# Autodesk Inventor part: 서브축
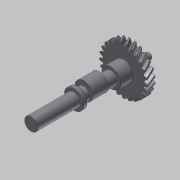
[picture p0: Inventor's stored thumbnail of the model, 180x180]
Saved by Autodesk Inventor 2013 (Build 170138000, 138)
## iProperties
Created: 2018-07
Part Number: 서브축
Material: 강철
Document SubType Name: Modeling
Designer: mduedu
Categories: <?xml version="1.0" encoding="UTF-16"?> <MemberInstance><Categories><FamilyTemplate><FamilyTemplateParameter ValueType="xs:double" Id="1" ObjectReferenceKey="da
Density: 7.85 g/cm^3
Mass: 513.764 g
Surface Area: 178.04 cm^2
Volume: 65.4477 cm^3
CustomPartVersion: 1
Author: mduedu
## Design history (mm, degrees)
sketch "Sketch1"
  geometry: C1 r 30.864 at (0, 0)
  constraints: 1 centre point
  dimensions: "d0" = 61.72879 diameter of C1 (= da_da)
extrude "Extrusion1" new body sketch "Sketch1" distance "d1" = 10 (= da_b); taper "d2" = 0 deg
workplane "Work Plane2"
sketch "Sketch2"
  geometry: C1 r 30.864 at (0, 0) reference; C2 r 29.013 at (0, 0)
  constraints: 1 centre point, 1 coincident
  dimensions: "d3" = 58.02632 diameter of C2 (= da_dw)
feature "피치 지름" sketch "Sketch2" dims "d4" = 10, "d5" = 0
workplane "Work Plane8"
workplane "Work Plane9"
feature "스퍼 기어" dims "da_b" = 10, "da_d" = 57.73503, "da_aw" = 44.1, "da_da" = 61.72879, "da_df" = 52.73503, "da_dw" = 58.02632, angle "da_beta" = 30 deg, "da_lefttooth" = 10, "da_righttooth" = 0
sketch "스케치3"
  geometry: C1 r 12.5 at (0, 0); 1 further point
  constraints: 1 centre point, 1 coincident
  dimensions: "d49" = 25 diameter of C1
extrude "돌출2" join sketch "스케치3" distance "d50" = 16; taper "d51" = 0 deg
sketch "스케치4"
  geometry: C1 r 8.5 at (0, 0); 1 further point
  constraints: 1 centre point, 1 coincident
  dimensions: "d52" = 17 diameter of C1
extrude "돌출3" join sketch "스케치4" distance "d53" = 103; taper "d54" = 0 deg
sketch "스케치5"
  geometry: C1 r 7.5 at (0, 0); 1 further point
  constraints: 1 centre point, 1 coincident
  dimensions: "d55" = 15 diameter of C1
extrude "돌출4" join sketch "스케치5" distance "d56" = 16; taper "d57" = 0 deg
sketch "스케치6"
  geometry: C1 r 4 at (0, 0); 1 further point
  constraints: 1 centre point, 1 coincident
  dimensions: "d58" = 8 diameter of C1
extrude "돌출5" join sketch "스케치6" distance "d59" = 7; taper "d60" = 0 deg
chamfer "모따기1" distance "d61" = 0.5; stored, may be unused: second distance "d62" = 2, angle "d63" = 45 deg
fillet "모깎기1" dims "d64" = 0.5
node "작업 평면11"
sketch "스케치7"
  geometry: C1 r 8.5 at (0, 0) reference; C2 r 11.5 at (0, -3); 1 further point
  constraints: 1 centre point, 1 tangent, 1 vertical alignment
  dimensions: "d66" = 23 diameter of C2; "d67" = 3 distance of point (0, 0) C2.centre (derived)
extrude "돌출6" join sketch "스케치7" stored distance "d68" = 20; taper "d69" = 0 deg
node "작업 평면12"
sketch "스케치8"
  geometry: C1 r 12.5 at (0, 0) reference; C2 r 12.5 at (0, 0) reference; 1 further point
extrude "돌출7" join sketch "스케치8" distance "d71" = 5; taper "d72" = 0 deg
chamfer "모따기2" distance "d73" = 0.5; stored, may be unused: second distance "d74" = 2, angle "d75" = 45 deg
body "Solid1"
body "Srf1"
node "투영된 루프1"
other parameters: "d16" = 44.1 (= da_aw), "d17" = 0, "d34" = 1.25664 (computed from da_z), "d39" = 0, "d41" = 0, "d43" = 44.1 (= da_aw), "d46" = 44.1 (= da_aw), "d47" = 0, "d48" = 0, "d65" = 25, "d70" = 48
